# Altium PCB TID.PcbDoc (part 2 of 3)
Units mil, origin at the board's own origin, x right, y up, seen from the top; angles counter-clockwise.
Board outline 3200 x 2650 mil, 4 copper layers (Top Layer, Mid-Layer 1, Mid-Layer 2, Bottom Layer), stack 61.2 mil thick; 193 components, 108 nets, 523 pads, 202 vias.
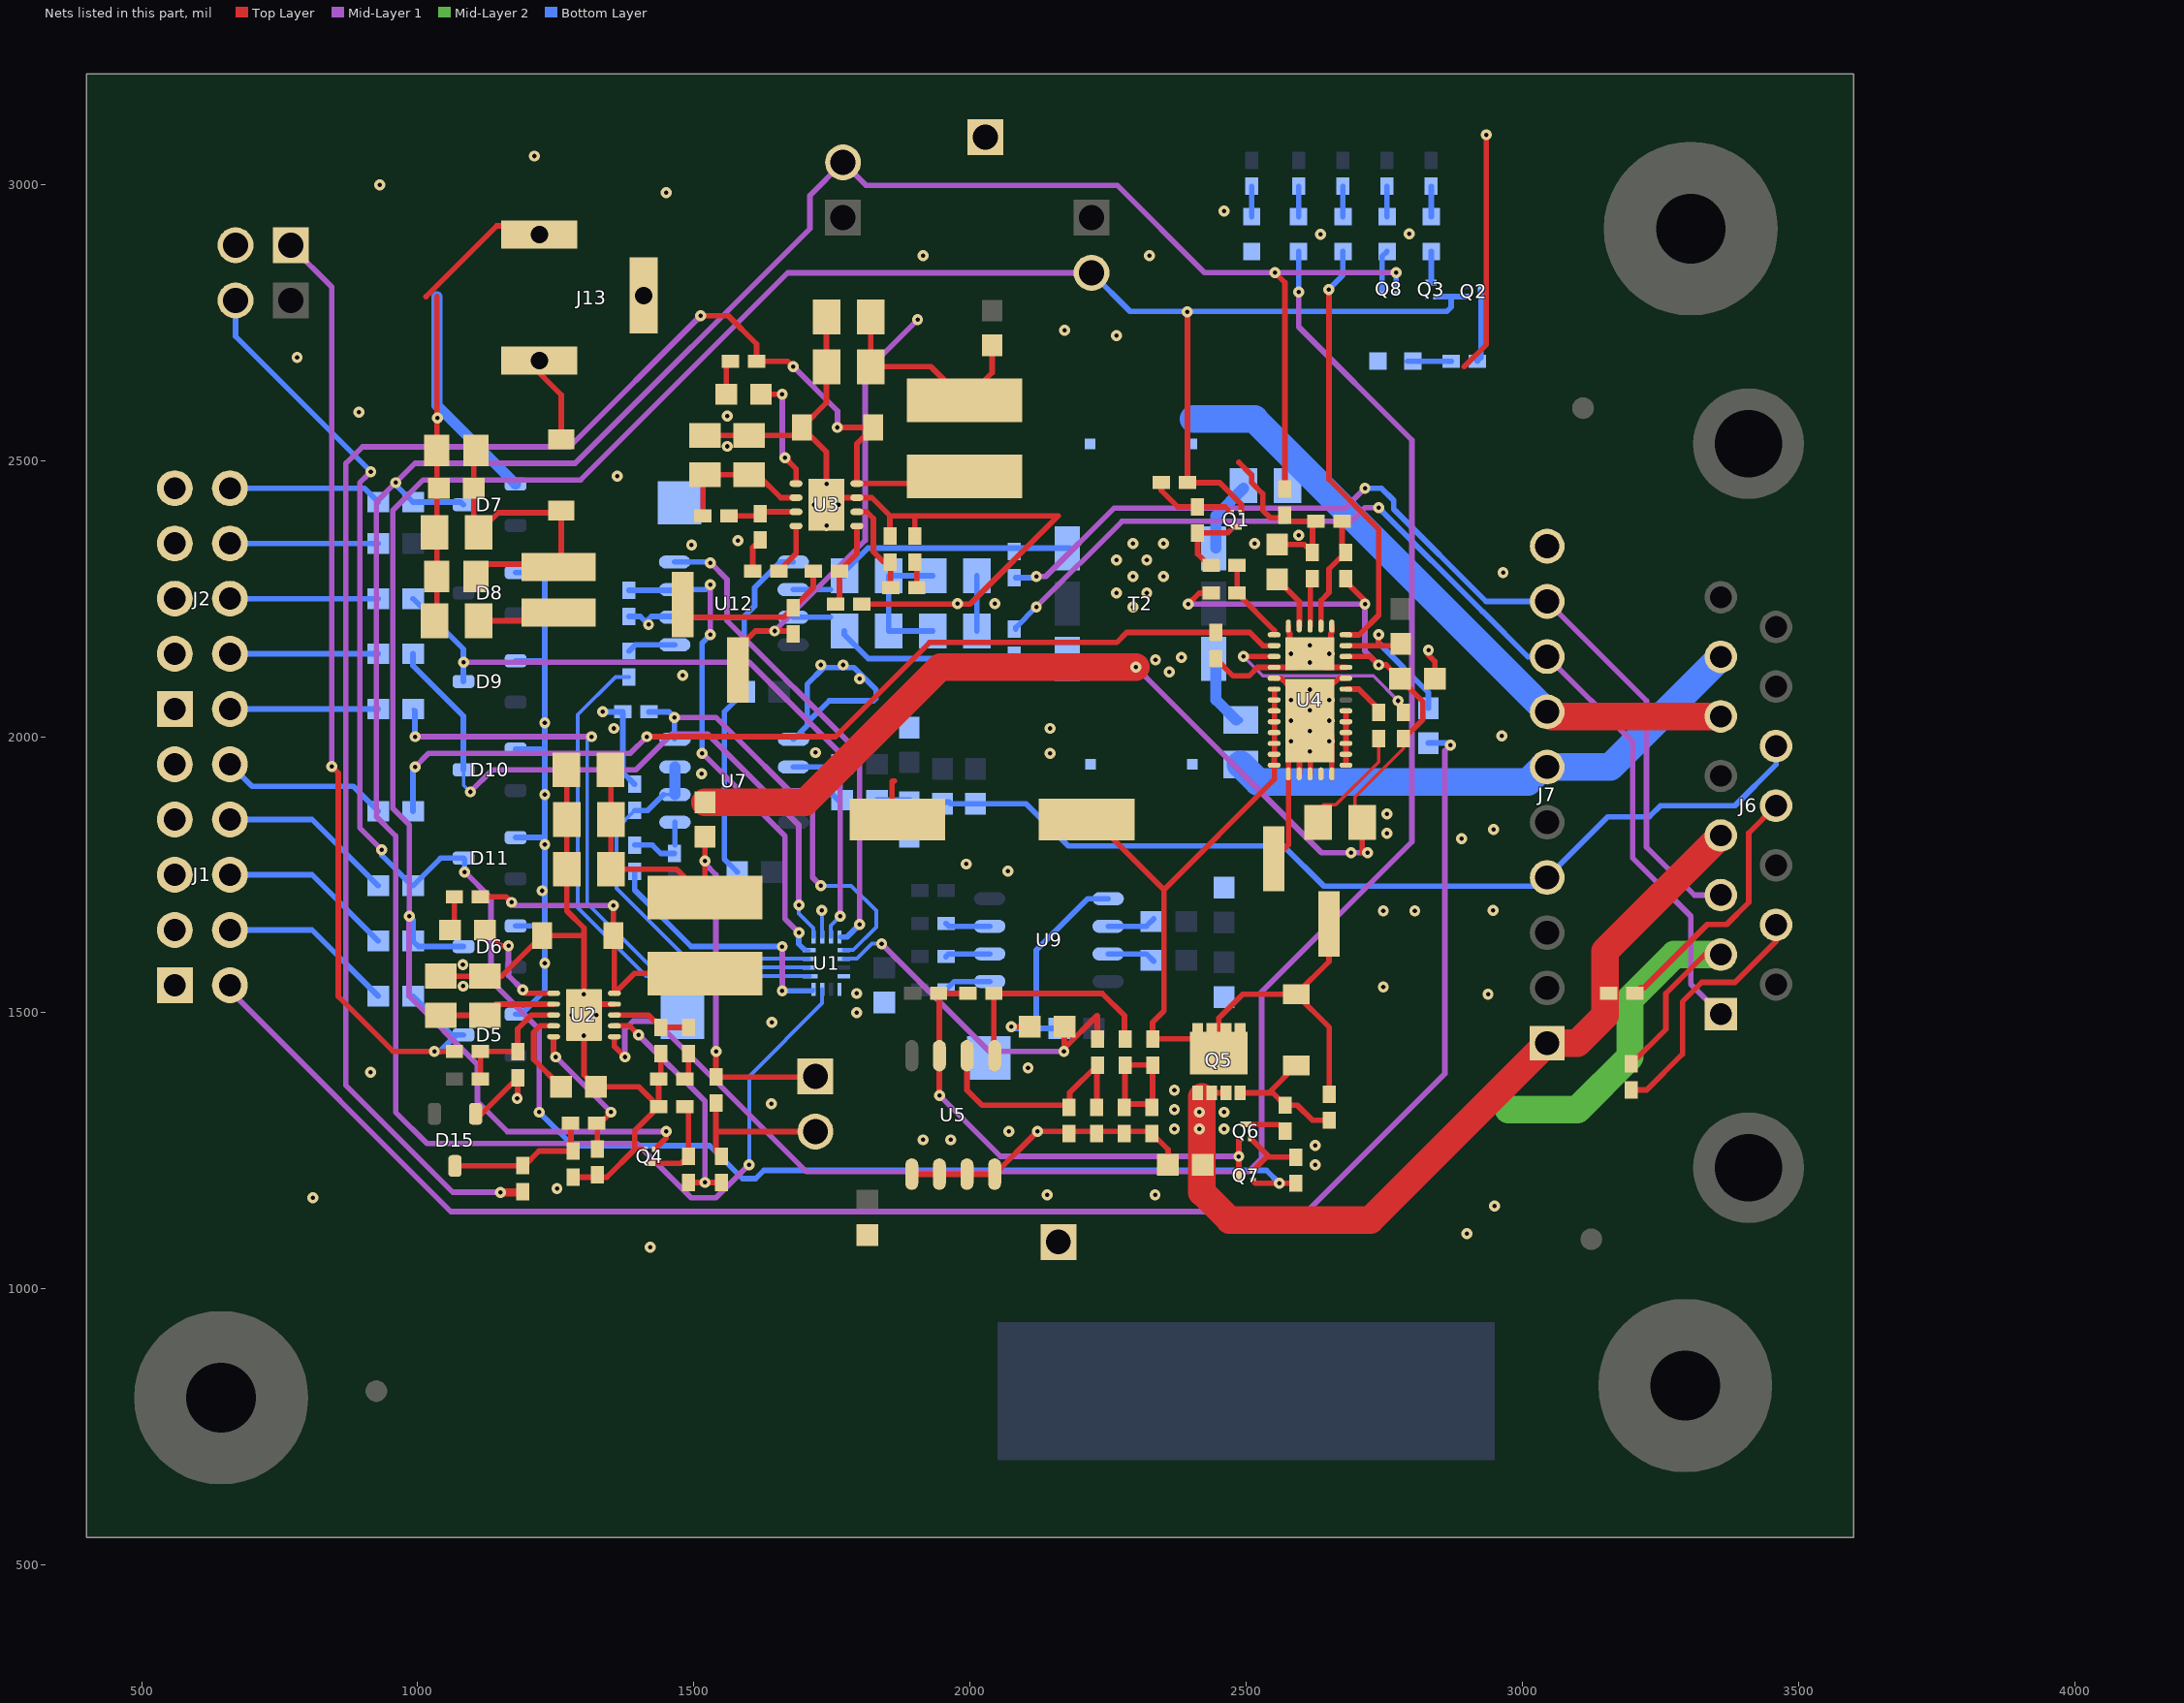
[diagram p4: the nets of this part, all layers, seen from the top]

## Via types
v1: diameter 20, hole 8, Top Layer to Bottom Layer, 200 vias
v2: diameter 19, hole 7.87, Top Layer to Bottom Layer, 2 vias

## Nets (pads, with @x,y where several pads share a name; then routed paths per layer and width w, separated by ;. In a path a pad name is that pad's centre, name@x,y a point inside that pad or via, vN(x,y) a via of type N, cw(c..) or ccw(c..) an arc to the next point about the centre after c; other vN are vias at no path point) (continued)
DATA-: C27.2 J6.13 J7.4 R22.2 R44.2 R62.2 | length 1817
  Bottom Layer w10: R62.2@1831.5,1885 1891.5,1885 1895,1881.5 1962.01,1881.5 1965,1878.5 2101.5,1878.5 2177.75,1802.25 2567.75,1802.25 2640.71,1729.29 3029.29,1729.29 J7.4@3045,1745 3155,1855 3230,1855 3250,1875 3385,1875 3459.37,1949.37 J6.13@3459.37,1982.87
DATA_IN: R56.1 U1.16 | length 481.3
  Mid-Layer 1 w10: v1(1660,1540) v1(1660,1620)
  Bottom Layer w6: U1.16@1713.62,1540 U1.16@1716.38,1542.76
  Bottom Layer w10: R56.1@1392.82,1756.47 1392.82,1722.18 1495,1620 1650,1620 v1(1660,1620) ; v1(1660,1540) U1.16@1713.62,1540
DATA_OUT: R67.2 U1.9 U7.4 | length 773.8
  Mid-Layer 1 w10: v1(1465,2035) 1540,2035 1715,1860 1715,1745 v1(1730,1730)
  Bottom Layer w6: U7.4@1465,1995.95 U7.4@1465.85,1995.09
  Bottom Layer w7: v1(1730,1730) 1785,1730 1830,1685 1830,1655 1788.62,1613.62 U1.9@1771.5,1613.62
  Bottom Layer w10: R67.2@1418.62,2045 1455,2045 v1(1465,2035) U7.4@1465,1995.95
DSL2+: C35.1 J6.6 J7.7 L5.2 | length 1177.3
  Top Layer w50: J7.7@3045,2045 3053.19,2036.81 J6.6@3359.37,2036.81
  Bottom Layer w50: 2405,2575 2515,2575 J7.7@3045,2045
DSL2-: C33.1 J6.7 J7.6 L4.1 | length 976.2
  Bottom Layer w50: C33.1@2490,1950 2521.64,1918.36 3010.29,1918.36 3036.93,1945 J7.6@3045,1945 3159.69,1945 J6.7@3359.37,2144.68
DSL4+: J6.3 J7.9 R72.2 | length 1823.7
  Mid-Layer 1 w10: v1(2120,2290) 2136.96,2290 2260.62,2413.66 2678.66,2413.66 v1(2715,2450) ; J7.9@3045,2245 3225,2065 3225,1800 3311.81,1713.19 J6.3@3359.37,1713.19
  Bottom Layer w10: R72.2@2082.82,2287.77 2117.77,2287.77 v1(2120,2290) ; v1(2715,2450) 2745,2450 2767.22,2427.78 2767.22,2412.22 2934.45,2245 J7.9@3045,2245 J7.9@3037.62,2237.62
DSL4-: J6.1 J7.8 R71.2 | length 1945
  Mid-Layer 1 w10: v1(2120,2235) 2275,2390 2690,2390 2715,2415 v1(2740,2415) ; J7.8@3045,2145 3200,1990 3200,1780 3305,1675 3305,1551.81 J6.1@3359.37,1497.44
  Bottom Layer w10: R71.2@2082.82,2195.02 2082.82,2197.82 v1(2120,2235) ; v1(2740,2415) 2746.89,2408.11 2746.89,2407.28 2927.04,2227.13 2927.87,2227.13 3010,2145 J7.8@3045,2145
DSL_EN: R84.2 U1.4 U12.3 | length 903.1
  Mid-Layer 1 w10: v1(1515,1970) 1665,1820 1665,1670 v1(1690,1645) ; v1(1530,2185) v1(1530,2275)
  Bottom Layer w6: v1(1530,2185) v1@1535,2185 ; U1.4@1701.57,1613.62 U1.4@1708.5,1613.62
  Bottom Layer w10: R84.2@1382.5,2265.02 U12.3@1463.84,2265.02 ; U12.3@1465.22,2266.39 1521.39,2266.39 v1(1530,2275) ; v1(1515,1970) 1515,2170 v1(1530,2185) ; v1(1690,1645) 1690,1624.74 U1.4@1698.83,1615.92
DSL_IN: R79.1 U1.1 | length 943.6
  Bottom Layer w6: U1.1@1709.54,1567.31 U1.1@1710.47,1566.38
  Bottom Layer w7: R79.1@1382.5,2107.77 1357.77,2107.77 1290,2040 1290,1690 1413.62,1566.38 U1.1@1710.47,1566.38
DSL_OUT: U1.8 U12.4 | length 877.3
  Mid-Layer 1 w10: v1(1530,2315) 1560,2285 1560,2210 1800,1970 v1(1800,1660)
  Bottom Layer w6: U12.4@1465.22,2316.39 U12.4@1466.61,2315 ; v1@1528.61,2316.39 v1(1530,2315)
  Bottom Layer w10: U12.4@1465.22,2316.39 v1@1528.61,2316.39 ; U1.8@1766.34,1637.43 1766.53,1637.24 1777.24,1637.24 v1(1800,1660)
EFUSE_PGOOD: D20.1 U4.31 | length 780.6
  Top Layer w10: v1(2649.5,2809.99) 2650.16,2809.33 2650.16,2465.82 2740,2375.98 2740,2220 2704.47,2184.47 U4.31@2681.02,2184.47
  Bottom Layer w10: v1(2649.5,2809.99) 2675.09,2835.58 D20.1@2675.09,2878.79
EN_TX_DATA: R68.2 U1.3 U7.2 U7.3 | length 692.4
  Bottom Layer w6: U7.2@1445.09,1895.09 U7.2@1465.85,1895.09 ; U1.3@1707.57,1598.81 U1.3@1708.5,1597.87
  Bottom Layer w7: R68.2@1392.82,1866.47 1360,1833.65 1360,1725 1487.13,1597.87 U1.3@1708.5,1597.87
  Bottom Layer w10: R68.2@1392.82,1866.47 1416.47,1866.47 U7.2@1445.09,1895.09
  Bottom Layer w20: U7.2@1465.85,1895.09 U7.3@1465.85,1945.09
GND: C2.2 C3.2 C4.2 C5.2 C6.2 C7.2 C8.2 C9.2 C11.2 C12.2 C13.2 C14.2 C15.2 C16.2 C17.2 C18.2 C19.2 C20.2 C21.2 C22.2 C23.2 C24.2 C25.1 C26.1 C27.1 C28.2 C29.1 C30.2 C31.1 C32.2 C34.2 C36.2 C38.2 C39.1 C40.1 C41.1 C42.1 D2.1 D5.1 D6.1 D7.1 D8.1 D9.1 D10.1 D11.1 D14.2 D15.1 D16.2 D17.1 J1.1 J1.3 J1.5 J1.7 J1.9 J2.1 J2.3 J2.5 J2.7 J2.9 J6.2 J7.10 J8.2 J12.1 J13.2 J13.3 J16.1 L4.2 Q1.2 Q3.2 Q4.2 Q6.2 Q7.2 Q8.2 R16.1 R19.1 R20.1 R29.2 R30.1 R35.1 R36.1 R40.1 R46.1 R48.1 R49.1 R52.1 R61.1 R67.1 R68.1 R70.1 R83.1 R84.1 R85.1 R86.1 TP1.1 TP2.1 TP3.1 U1.6 U1.12 U1.13 U2.9 U2.11 U3.7 U3.9 U4.4 U4.28 U4.32 U4.36 U4.37 U5.1 U5.2 U5.3 U5.4 U7.5 U9.5 U12.2 U12.5 | length 10271.4
  Top Layer w10: 1014.96,2797 1142.96,2925 J13.2@1200,2925 ; C19.2@1030,2210 1034.57,2214.56 C16.2@1034.57,2290 1034.57,2374.56 C30.2@1034.57,2518.7 1034.57,2796.61 1034.96,2797 ; C6.2@1041.8,1566.3 C5.2@1121.8,1566.3 1151.83,1566.3 D14.2@1225.53,1640 1301.05,1640 ; D15.1@1107.4,1317.24 1115.9,1317.24 R19.1@1181.05,1382.4 1181.05,1346.05 v1(1180,1345) ; C34.2@1270,1940 1270,1850 C3.2@1270,1760 1270,1684.47 1301.05,1653.42 1301.05,1640 ; R30.1@1281.05,1202.4 1342.4,1202.4 1392.8,1252.8 ; U2.11@1320.73,1515.7 U2.9@1356.17,1515.7 ; Q4.2@1410.87,1252.8 1392.8,1252.8 ; C8.2@1440,1426.38 1440,1383.62 C9.2@1436.38,1380 R29.2@1436.38,1330 ; C11.2@1520,2545.43 C12.2@1600,2545.43 1680.96,2545.43 D16.2@1695.53,2560 ; R36.1@1606.38,2300 1606.38,2342.76 R35.1@1620,2356.38 ; C13.2@1740,2760 C14.2@1740,2670 1740,2604.47 D16.2@1695.53,2560 ; R40.1@1803.62,2240 2000,2240 2160,2400 1900,2400 ; C15.2@1855,2363.62 1855,2400 ; C22.2@1858.74,1850 1858.74,1918.74 1859.72,1919.72 1863.36,1919.72 ; U5.1@1894.5,1207.72 U5.2@1944.5,1207.72 U5.3@1994.5,1207.72 U5.4@2044.5,1207.72 v1(2122.2,1285.41) C24.2@2330.6,1285.41 ; C20.2@1900,2363.62 1900,2400 ; v1(2075,1475) C31.1@2108,1475 ; C24.2@2329.5,1281.38 2358.5,1252.37 C21.2@2358.5,1225 C21.2@2353.5,1220 ; R85.1@2346.38,2460 2346.38,2446.06 2376.22,2416.22 R86.1@2412.13,2416.22 2462.17,2416.22 Q1.2@2472.99,2405.39 ; R46.1@2445,2141.38 2476.38,2110 2505,2110 2520.41,2125.41 U4.37@2591.73,2125.41 ; 2486.74,2496.74 2510,2473.48 2510,2460 2530,2440 2530,2410 2543.62,2396.38 2570,2396.38 2576.38,2390 R49.1@2626.38,2390 2620,2383.62 R48.1@2620,2333.62 2605.77,2347.85 C23.2@2556.06,2347.85 ; Q6.2@2508.63,1272.2 2542.22,1238.62 ; Q7.2@2512.3,1214.13 2536.78,1238.62 2542.22,1238.62 ; U4.36@2576.69,2200.22 2576.69,2189.11 2578.78,2187.03 U4.37@2578.78,2175.53 ; R52.1@2589.5,1238.62 2542.22,1238.62 ; U4.37@2640.39,2125.41 U4.28@2681.02,2125.41 ; U4.37@2653.35,2175.53 2653.35,2187.03 2655.43,2189.11 U4.32@2655.43,2200.22 ; v1(2830,2156.5) 2830,2147.99 2841.5,2136.5 C25.1@2841.5,2105 ; 2895,2670 2935,2710 v1(2935,3090) ; R70.1@3197.27,1407.48 3260,1470.21 3260,1535 3330.32,1605.32 J6.2@3359.37,1605.32 ; 1301.05,1640 U2.11@1301.05,1496.02 1301.05,1387.52 C7.2@1322.54,1366.02 1400.36,1366.02 R29.2@1436.38,1330 ; 1392.8,1252.8 1392.8,1286.42 R29.2@1436.38,1330 ; D16.2@1695.53,2560 1740,2515.53 U3.9@1740,2420 1752.8,2432.8 U3.7@1795.12,2432.8 1822.2,2432.8 1855,2400 ; 1855,2400 1900,2400
  Mid-Layer 2 w50: 2975,1325 3100,1325 3195,1420 3195,1525 3275.32,1605.32 J6.2@3359.37,1605.32
  Bottom Layer w6: v1(1731.92,1685.6) 1731.92,1673.08 1732.13,1672.87
  Bottom Layer w7: U1.6@1732.13,1637.24 1732.13,1672.87
  Bottom Layer w10: D5.1@1177.24,1497.4 1187.4,1497.4 1230,1540 1230,2285 1217.6,2297.4 D8.1@1177.24,2297.4 ; D6.1@1177.24,1657.4 1227.4,1657.4 ; D11.1@1177.24,1817.4 1227.4,1817.4 ; D10.1@1177.24,1977.4 1227.4,1977.4 ; D9.1@1177.24,2137.4 1227.4,2137.4 ; v1(1335,2045) R67.1@1371.38,2045 1371.38,1935.16 R68.1@1392.82,1913.72 ; R84.1@1382.5,2217.77 1402.84,2217.77 1417.72,2202.9 v1(1417.94,2202.9) 1417.94,2212.53 1423.17,2217.77 U12.2@1463.84,2217.77 ; U12.2@1465.22,2216.39 1589.93,2216.39 ; C39.1@1578.5,1755 1555,1778.5 1555,2045.07 C40.1@1591.32,2081.39 1591.32,2215 1589.93,2216.39 ; U12.5@1679.79,2316.39 1656.39,2316.39 1610,2270 1610,2236.46 1589.93,2216.39 ; U7.5@1680.42,1995.09 1705,2019.68 1705,2025 ; C36.2@2012.5,2191.39 C38.2@2012.5,2291.39 ; v1(2075,1475) 2078.29,1471.71 2120,1471.71 ; C41.1@2161.32,1471.71 2120,1471.71 ; U9.5@2250.1,1706.71 2213.29,1706.71 2120,1613.42 2120,1471.71 ; J7.10@3045,2345 J7.10@3046.38,2346.38 ; 1705,2025 1745,2065 1825,2065 1830,2070 1830,2085 1790,2125 1735,2125 1705,2095 1705,2025
  Bottom Layer w20: 1034.96,2797 1034.96,2599.69 D7.1@1177.24,2457.4
  other v1: 1421.24,1075.75 2900,1100 2950,1150 810,1165 2140,1170 2335,1170 1252.05,1181.67 2625,1225 2625.33,1259.67 1915,1270 1965,1270 2070,1285 1640,1335 914.44,1392.07 2104.97,1400.56 1301.05,1458.62 1641.21,1482.42 1278.41,1496.02 1323.69,1496.02 1795,1500 1301.05,1533.42 2937.93,1533.32 1795,1535 2748.33,1546.61 1081.93,1548.19 1081.73,1587.46 1230,1590 2748.33,1684.77 2805.34,1684.77 2946.88,1685.27 1225.19,1721.02 2068.62,1756.26 1992.78,1769.33 1230,1805 2889.87,1815.49 2947.96,1831.83 1230,1895 1514.17,1932.98 2145,1970 1720.32,1971.2 2962.62,2001.62 1355,2015 2145,2015 1230,2025 1800,2105 1479.4,2111.23 1730,2130 1770,2130 2615.71,2134.38 2581.26,2150.13 2650.16,2150.13 2615.71,2165.87 1977.61,2240.9 2045.19,2240.65 2965.14,2297.36 1495.87,2347.08 2515,2350 1580,2355 2595,2365 1740,2382.6 1717.36,2420 1762.64,2420 1740,2457.4 1361.48,2471.59 1560.15,2525.8 1035.82,2577.38 1560.15,2580.52 893.6,2587.4 781.53,2686.81 2265.46,2725.97 2171.26,2735.68 1914.69,2870.98 2325.01,2870.92 2634.61,2909.71 2795.4,2910.41 2459.71,2952.02 1450,2985 931.19,2999.24 1211.13,3051.47
HI_V_SEL: D6.3 J9.2 Q1.1 Q2.1 Q3.1 Q4.1 R7.2 R85.2 | length 4320.2
  Top Layer w10: Q4.1@1429.13,1252.8 1450,1273.66 v1(1450,1285) ; J9.2@2220,2840 J9.2@2220.53,2840.53 ; v1@2393.2,2769.38 v1(2393.62,2768.96) R85.2@2393.62,2460 2452.13,2460 2491.26,2420.87 Q1.1@2491.26,2405.39
  Mid-Layer 1 w10: v1(1450,1285) 1162.22,1285 1108.11,1339.11 1108.11,1406.46 984.29,1530.28 984.29,1674.29 v1(985,1675) 985,1840 955,1870 955,2410 1010,2465 1295,2465 1670,2840 J9.2@2220,2840
  Bottom Layer w10: v1(985,1675) 991.5,1668.5 R7.2@991.5,1630 1001.5,1620 D6.3@1082.76,1620 ; J9.2@2220,2840 2289.82,2770.18 2863.37,2770.18 2871.08,2777.89 2871.08,2797.06 ; 2845.1,2797.06 2871.08,2797.06 ; Q2.1@2897.05,2797.06 2871.08,2797.06
HIPERFACE: D7.3 J10.2 Q8.1 R12.2 R83.2 U1.15 | length 5004.1
  Top Layer w10: v1(2551.95,2840.61) 2570,2822.56 R83.2@2570,2448.62
  Mid-Layer 1 w10: v1(1600,1225) 1540,1165 1495.24,1165 1396.92,1263.33 1016.67,1263.33 960,1320 960,1820 925,1855 925,2425 v1(960,2460) 995.01,2495.01 1285.01,2495.01 1710,2920 1710,2980 J10.2@1770,3040 1811.48,2998.52 2266.48,2998.52 2424.53,2840.47 2771.17,2840.47 v1(2771.45,2840.19)
  Bottom Layer w7: v1(1600,1225) 1600,1385 1732.13,1517.13 U1.15@1732.13,1542.76
  Bottom Layer w10: v1(960,2460) 960,2456.5 R12.2@991.5,2425 1077.76,2425 D7.3@1082.76,2420 ; v1@2771.3,2840.34 v1(2771.45,2840.19) ; Q8.1@2771.51,2819.62 v1@2771.51,2842.57
LOAD_SW_CTRL: D11.3 J11.2 Q7.1 R9.2 R52.2 | length 3326.8
  Top Layer w10: Q7.1@2512.3,1195.87 2516.78,1191.38 v1(2560,1191.38) R52.2@2589.5,1191.38 R52.2@2582.77,1198.11
  Mid-Layer 1 w10: v1@910,2475 895,2460 895,1835 v1(935,1795) ; v1(1085,1755) 1132.57,1707.43 1132.57,1557.71 1220,1470.28 v1(1220,1320)
  Bottom Layer w10: J11.2@670,2790 670,2725 v1(915,2480) ; v1(935,1795) 935,1785.03 990.03,1730 R9.2@991.5,1730 1041.5,1780 D11.3@1082.76,1780 1085,1777.76 v1(1085,1755) ; v1(1220,1320) 1280.65,1259.35 1528.32,1259.35 1588.08,1199.6 1611.64,1199.6 1626.8,1214.76 2536.62,1214.76 v1(2560,1191.38)
NetC1_1: C1.1 R18.1 | length 73.3
  Top Layer w10: C1.1@1058.5,1640 1066.38,1647.87 R18.1@1066.38,1710
NetC1_2: C1.2 U2.1 | length 211.3
  Top Layer w10: C1.2@1123.05,1650 C1.2@1121.5,1650 1149.87,1621.63 v1(1164.27,1621.63) ; v1(1190,1541.58) 1190,1540 1194.61,1535.39 U2.1@1245.93,1535.39
  Mid-Layer 1 w10: v1@1162.95,1617.05 1164.27,1618.37 v1(1164.27,1621.63) ; v1(1164.27,1621.63) 1164.28,1567.3 v1(1190,1541.58)
NetC2_1: C2.1 C3.1 C34.1 J3.1 L1.2 R17.1 R24.2 | length 1016.2
  Top Layer w10: C34.1@1350,1940 1350,1850 C3.1@1350,1760 1468.9,1760 L1.2@1509.45,1719.45 ; L1.2@1520,1730 R17.1@1520,1818.5 ; v1(1540,1430) R24.2@1540,1383.62 1693.62,1383.62 J3.1@1710,1400
  Mid-Layer 1 w10: v1@1520,1770 1540,1750 v1(1540,1430)
  other v1: 1520,1775
NetC4_1: C4.1 R16.2 R50.1 U5.6 | length 427.3
  Top Layer w10: U5.6@1994.5,1422.28 1994.5,1360 2021.84,1332.66 2180.6,1332.66 2180.6,1355.41 2229.5,1404.31 C4.1@2229.5,1328.62
NetC7_1: C7.1 U2.4 | length 159.9
  Top Layer w10: U2.4@1245.93,1476.33 1221.81,1476.33 1210,1464.52 1210,1415.57 C7.1@1259.55,1366.02
NetC8_1: C8.1 R26.2 U2.8 | length 143.1
  Top Layer w10: U2.8@1356.17,1496.02 1417.6,1496.02 C8.1@1440,1473.62 R26.2@1490,1473.62
NetC9_1: C9.1 R26.1 | length 49
  Top Layer w10: C9.1@1483.62,1380 1490,1386.38 R26.1@1490,1426.38
NetC10_1: C10.1 R31.1 | length 63.3
  Top Layer w10: C10.1@1558.5,2620 1558.5,2672.13 R31.1@1566.38,2680
NetC10_2: C10.2 U3.1 | length 210.4
  Top Layer w10: C10.2@1621.5,2620 v1(1660,2620) ; v1(1665,2505) 1684.88,2485.12 U3.1@1684.88,2458.39
  Mid-Layer 1 w10: v1(1660,2620) 1660,2510 v1(1665,2505)
NetC13_1: C13.1 C14.1 J5.1 L2.2 R32.1 R39.2 | length 1242.7
  Top Layer w10: J5.1@1580,2100 J5.1@1593.62,2100 ; J5.1@1580,2122.5 1580,2160 1611.39,2191.39 v1(1646.08,2191.39) 1674.98,2191.39 R39.2@1680,2186.38 ; C13.1@1820,2760 C14.1@1820,2670 1928.9,2670 L2.2@1990,2608.9 1994.72,2613.62 2040,2658.9 R32.1@2040,2708.5
  Mid-Layer 1 w10: v1(1646.08,2191.39) 1810,2355.32 1810,2660 v1(1905,2755)
NetC15_1: C15.1 R37.2 U3.6 | length 179.6
  Top Layer w10: U3.6@1795.12,2407.2 1812.8,2407.2 1825,2395 1825,2335 1843.62,2316.38 C15.1@1855,2316.38 1856.38,2315 R37.2@1856.38,2270
NetC16_1: C16.1 C17.1 C18.1 C30.1 D18.1 L6.1 | length 589.6
  Top Layer w10: C16.1@1105.44,2290 1128,2312.56 1270,2312.56 1260,2322.56 1260,2405.53 1145.54,2405.53 C17.1@1110,2370 1101.5,2378.5 C18.1@1101.5,2450 1101.5,2514.76 C30.1@1105.44,2518.7
NetC20_1: C20.1 R37.1 | length 47.9
  Top Layer w10: C20.1@1900,2316.38 1903.62,2312.76 R37.1@1903.62,2270
NetC23_1: C23.1 U4.35 | length 101.3
  Top Layer w10: C23.1@2556.06,2284.86 2596.38,2244.55 U4.35@2596.38,2200.22
NetC24_1: C24.1 R59.1 R60.1 R61.2 | length 245.4
  Top Layer w10: C24.1@2329.5,1335 2282.94,1335 2280.6,1332.66 R59.1@2280.6,1405.41 R60.1@2330.6,1405.41 C24.1@2330.6,1332.66
NetC33_2: C33.2 T2.6 | length 134.6
  Bottom Layer w10: C33.2@2482,2030 C33.2@2490,2030
  Bottom Layer w20: T2.6@2445.32,2141.39 2445.32,2066.68 C33.2@2482,2030
NetC35_2: C35.2 T2.4 | length 134.2
  Bottom Layer w10: C35.2@2495,2450 C35.2@2500,2450
  Bottom Layer w20: T2.4@2445.32,2341.39 2445.32,2400.32 C35.2@2495,2450
NetC36_1: C36.1 C38.1 R80.1 R82.2 | length 260
  Bottom Layer w10: C36.1@1932.5,2191.39 R80.1@1852.5,2191.39 R82.2@1852.5,2291.39 C38.1@1932.5,2291.39
NetD1_1: D1.1 Q3.3 | length 56.3
  Bottom Layer w10: Q3.3@2834.9,2822.62 2835.09,2822.82 D1.1@2835.09,2878.79
NetD1_2: D1.2 R3.1 | length 54.9
  Bottom Layer w10: D1.2@2835.09,2941.78 R3.1@2835.09,2996.67
NetD2_2: D2.2 R4.1 | length 79.2
  Bottom Layer w10: D2.2@2792.16,2680 D2.2@2801.5,2680 R4.1@2871.38,2680
NetD13_2: D13.2 R13.1 | length 54.9
  Bottom Layer w10: D13.2@2595.09,2941.78 R13.1@2595.09,2996.67
NetD14_1: D14.1 L1.1 R18.2 U2.10 | length 563.3
  Top Layer w10: R18.2@1113.62,1710 1160,1710 v1(1170,1700) ; D14.1@1354.47,1640 v1(1354.47,1694.47) ; D14.1@1356.17,1618.3 U2.10@1356.17,1535.39 1391.88,1571.1 L1.1@1520,1571.1
  Mid-Layer 1 w10: v1(1170,1700) 1175.53,1694.47 v1(1354.47,1694.47)
NetD15_3: D15.3 R25.1 R27.2 R30.2 | length 280.1
  Top Layer w10: D15.3@1070,1222.76 1192.76,1222.76 1219.64,1249.64 R30.2@1281.05,1249.64 1277.43,1253.26 R25.1@1277.43,1306.02
NetD17_2: D17.2 R34.1 | length 54.9
  Bottom Layer w10: D17.2@2510.05,2941.78 R34.1@2510.05,2996.67
NetD18_2: D18.2 J13.1 | length 169.4
  Top Layer w10: J13.1@1200,2679 1260,2619 D18.2@1260,2534.47
NetD19_1: D19.1 Q8.3 | length 72.3
  Bottom Layer w10: Q8.3@2745.86,2810.35 2745.86,2869.56 D19.1@2755.09,2878.79
NetD19_2: D19.2 R81.1 | length 54.9
  Bottom Layer w10: D19.2@2755.09,2941.78 R81.1@2755.09,2996.67
NetD20_2: D20.2 R43.1 | length 54.9
  Bottom Layer w10: D20.2@2675.09,2941.78 R43.1@2675.09,2996.67
NetD21_2: D21.2 Q5.4 R45.1 R47.2 | length 252.2
  Top Layer w10: Q5.4@2488.99,1355.06 2541.09,1355.06 ; D21.2@2590.6,1404.57 2541.09,1355.06 ; R45.1@2650.6,1305.41 2619.91,1305.41 2592.67,1332.66 R47.2@2570.6,1332.66 2548.2,1355.06 2541.09,1355.06
NetJ1_2: J1.2 R1.1 | length 3119.8
  Mid-Layer 1 w10: J1.2@660,1550 660,1540 1060,1140 2610,1140 2859.76,1389.76 2859.76,1974.76 v1(2870,1985)
  Bottom Layer w6: v1@2866.5,1988.5 v1(2870,1985)
  Bottom Layer w10: R1.1@2830,1988.5 v1@2866.5,1988.5
NetJ1_4: J1.4 R5.1 | length 318.2
  Bottom Layer w10: J1.4@660,1650 808.5,1650 R5.1@928.5,1530
NetJ1_6: J1.6 R7.1 | length 318.2
  Bottom Layer w10: J1.6@660,1750 808.5,1750 R7.1@928.5,1630
NetJ1_8: J1.8 R9.1 | length 318.2
  Bottom Layer w10: J1.8@660,1850 808.5,1850 R9.1@928.5,1730
NetJ1_10: J1.10 R11.1 | length 303.7
  Bottom Layer w10: J1.10@660,1950 700,1910 883.5,1910 R11.1@928.5,1865
NetJ2_2: J2.2 R2.1 | length 268.5
  Bottom Layer w10: J2.2@660,2050 R2.1@928.5,2050
NetJ2_4: J2.4 R6.1 | length 268.5
  Bottom Layer w10: J2.4@660,2150 R6.1@928.5,2150
NetJ2_6: J2.6 R8.1 | length 268.5
  Bottom Layer w10: J2.6@660,2250 R8.1@928.5,2250
NetJ2_8: J2.8 R10.1 | length 268.5
  Bottom Layer w10: J2.8@660,2350 R10.1@928.5,2350
NetJ2_10: J2.10 R12.1 | length 278.9
  Bottom Layer w10: J2.10@660,2450 903.5,2450 R12.1@928.5,2425
NetJ3_2: J3.2 R23.1 R24.1 | length 280.4
  Top Layer w10: R24.1@1540,1336.38 1540,1249.84 R23.1@1550,1239.84 ; 1540.23,1284.78 J3.2@1720,1285
NetJ5_2: J5.2 R38.2 R39.1 | length 273.6
  Top Layer w10: J5.2@1495,2216.39 1662.77,2216.39 R39.1@1680,2233.62 1716.38,2270 R38.2@1716.38,2300
NetJ6_10: J6.10 R70.2 | length 459.1
  Top Layer w10: R70.2@3197.27,1360.24 3225.24,1360.24 3290,1425 3290,1520 3325,1555 3385,1555 3459.37,1629.37 J6.10@3459.37,1659.25
NetJ6_12: J6.12 R69.2 | length 470.2
  Top Layer w10: R69.2@3203.62,1535 3213.62,1545 3220,1545 3335,1660 3370,1660 3410,1700 3410,1825.63 J6.12@3459.37,1875
NetJ15_1: J15.1 R21.2 R42.1 U4.5 U4.14 U4.15 U4.16 U4.17 U4.18 U4.27 U4.38 | length 880.4
  Top Layer w6: 2640,1876.51 2662.31,1876.51 2740,1954.2 R21.2@2740,1996.38
  Top Layer w10: J15.1@2550,1777.5 2576.69,1804.19 U4.38@2576.69,1989.31 ; U4.5@2551.1,2105.73 2563.39,2105.73 ; 2565.48,2103.64 2575.79,2093.33 U4.38@2575.79,2068.96 ; U4.38@2580,2064.74 U4.38@2616.06,2028.68 ; U4.38@2580.28,1992.89 U4.38@2596.38,2009 ; U4.15@2596.38,1932.5 U4.38@2596.38,2009 ; U4.16@2616.06,1932.5 U4.38@2616.06,2028.68 ; U4.38@2616.06,2040.77 U4.38@2616.06,2028.68 ; R42.1@2630,1845 R42.1@2630,1855 ; U4.38@2635.75,2009 U4.38@2655.43,1989.31 ; U4.38@2653.89,2094.03 2668.73,2105.73 U4.27@2681.02,2105.73 ; U4.18@2654.83,1924.8 U4.38@2654.83,2001.3 ; U4.38@2596.38,2009 U4.38@2616.06,2028.68
  other v1: 2615.71,1972.96 2581.26,1991.66 2650.16,1991.66 2615.71,2010.36 2581.26,2029.06 2650.16,2029.06 2615.71,2047.76 2581.26,2066.46 2650.16,2066.46 2615.71,2085.16
NetQ1_3: Q1.3 R55.1 R86.2 | length 145.6
  Top Layer w10: R55.1@2436.38,2310 2432.85,2310 2412.13,2330.72 R86.2@2412.13,2368.98 2466.41,2368.98 2477.24,2379.8 Q1.3@2482.13,2379.8
NetQ2_3: Q2.3 R4.2 | length 128.9
  Bottom Layer w10: R4.2@2918.62,2680 2924.98,2686.35 Q2.3@2924.98,2806.25
NetQ4_3: Q4.3 R28.2 R29.1 | length 167.9
  Top Layer w10: Q4.3@1420,1227.2 1477.2,1227.2 R28.2@1490,1240 1490,1323.62 R29.1@1483.62,1330
NetQ6_1: Q6.1 Q7.3 R51.1 R57.2 U5.7 | length 891.8
  Top Layer w10: R51.1@1943.12,1535 R57.2@1995.88,1535 ; v1(1944.5,1350.5) U5.7@1944.5,1422.28 R51.1@1944.5,1533.62 ; Q7.3@2486.7,1205 v1(2486.7,1240) 2486.7,1270.39 2488.52,1272.2
  Mid-Layer 1 w10: v1(1944.5,1350.5) 2055,1240 v1(2486.7,1240)
NetQ6_3: Q6.3 R47.1 | length 76.2
  Top Layer w10: Q6.3@2499.5,1297.8 2558.22,1297.8 R47.1@2570.6,1285.41
NetR14_1: R14.1 R15.1 R19.2 U2.3 | length 234.2
  Top Layer w10: R14.1@1113.62,1380 R15.1@1113.62,1430 1180.69,1430 R19.2@1181.05,1429.64 1181.05,1471.05 1206.02,1496.02 U2.3@1245.93,1496.02
NetR20_2: R20.2 R25.2 U2.5 | length 265.4
  Top Layer w10: U2.5@1245.93,1456.65 1245.93,1424.07 v1(1250,1420) ; R20.2@1323.62,1255 R20.2@1325,1253.62 1325,1305.69 1324.67,1306.02 1336.02,1306.02 v1(1350,1320)
  Mid-Layer 1 w10: v1(1250,1420) v1(1350,1320)
NetR21_1: R21.1 U4.26 | length 73.9
  Top Layer w10: U4.26@2681.02,2086.04 2703.96,2086.04 R21.1@2740,2050
NetR23_2: R23.2 R28.1 U2.7 | length 427.6
  Top Layer w10: U2.7@1356.17,1476.33 1383.67,1476.33 v1(1400,1460) ; R28.1@1490,1192.76 1549.84,1192.76 R23.2@1550,1192.6
  Mid-Layer 1 w10: v1(1400,1460) 1520,1340 v1(1520,1192.76)
NetR33_2: R33.2 R35.2 U3.3 | length 124.2
  Top Layer w10: R33.2@1563.62,2400 1616.38,2400 R35.2@1620,2403.62 1623.58,2407.2 U3.3@1684.88,2407.2
NetR36_2: R36.2 U3.4 | length 94.6
  Top Layer w10: R36.2@1653.62,2300 1684.88,2331.26 U3.4@1684.88,2381.61
NetR38_1: R38.1 R40.2 U3.5 | length 157.7
  Top Layer w10: R40.2@1756.38,2240 1763.62,2247.24 R38.1@1763.62,2300 1795.12,2331.5 U3.5@1795.12,2381.61
NetR41_1: R41.1 U4.3 | length 399.8
  Top Layer w6: v1(2775,2065) 2785,2055 R41.1@2785,2043.62 ; R41.1@2782.5,2046.12 R41.1@2782.5,2051.12
  Top Layer w10: v1(2495,2145) 2495.1,2145.1 U4.3@2551.1,2145.1
  Mid-Layer 1 w6: v1(2495,2145) 2530,2110 2730,2110 v1(2775,2065)
NetR48_2: R48.2 U4.34 | length 72.2
  Top Layer w10: U4.34@2616.06,2200.22 R48.2@2616.06,2272.44
NetR49_2: R49.2 R53.2 U4.33 | length 201.7
  Top Layer w10: U4.33@2635.75,2200.22 2635.75,2246.9 2650,2261.15 2650,2303.62 R53.2@2680,2333.62 ; R53.2@2673.62,2340 R49.2@2673.62,2390
NetR54_2: R54.2 R55.2 U4.1 | length 153.5
  Top Layer w10: R55.2@2483.62,2310 R54.2@2483.62,2260 2551.1,2192.52 U4.1@2551.1,2184.47
NetR56_2: R56.2 R63.1 U7.1 | length 119.1
  Bottom Layer w10: R56.2@1392.82,1803.72 1424.91,1803.72 1440,1788.62 R63.1@1465,1788.62 ; 1465.85,1804.47 U7.1@1465.85,1845.09
NetR57_1: R57.1 R59.2 U5.5 | length 407.1
  Top Layer w10: U5.5@2043.12,1423.66 R57.1@2043.12,1535 2239.5,1535 2279.5,1495 2279.5,1453.76 R59.2@2280.6,1452.66
NetR62_1: R62.1 U7.7 | length 87.6
  Bottom Layer w10: U7.7@1680.42,1895.09 1751.3,1895.09 R62.1@1763.13,1883.26
NetR66_1: R66.1 U7.6 | length 88
  Bottom Layer w10: U7.6@1680.42,1945.09 1749.32,1945.09 R66.1@1762.82,1958.6
NetR71_1: R71.1 R80.2 T2.1 U12.7 | length 500.1
  Bottom Layer w10: U12.7@1679.79,2216.39 R80.2@1747.5,2216.39 ; R80.2@1772.5,2191.39 1772.5,2184.81 1815.92,2141.39 T2.1@2180.32,2141.39
NetR72_1: R72.1 R82.1 T2.3 U12.6 | length 500.7
  Bottom Layer w10: U12.6@1679.79,2266.39 R82.1@1747.5,2266.39 ; R82.1@1772.5,2291.39 1772.5,2299.05 1814.84,2341.39 T2.3@2180.32,2341.39
NetR73_1: R73.1 U9.7 | length 88.3
  Bottom Layer w10: U9.7@2250.1,1606.71 2319.32,1606.71 R73.1@2332.82,1593.2
NetR75_1: R75.1 U9.3 | length 81.2
  Bottom Layer w10: R75.1@1956.44,1661.71 1961.44,1656.71 U9.3@2035.54,1656.71
NetR76_1: R76.1 U9.2 | length 81.2
  Bottom Layer w10: R76.1@1956.44,1601.71 1961.44,1606.71 U9.2@2035.54,1606.71
NetR77_1: R77.1 U9.1 | length 85.3
  Bottom Layer w10: R77.1@1956.44,1541.71 1971.44,1556.71 U9.1@2035.54,1556.71
NetR78_1: R78.1 U9.6 | length 88.3
  Bottom Layer w10: U9.6@2250.1,1656.71 2319.32,1656.71 R78.1@2332.82,1670.21
NetR79_2: R79.2 U12.1 | length 87.4
  Bottom Layer w10: R79.2@1382.5,2155.02 1393.88,2166.39 U12.1@1465.22,2166.39
NetU4_19: U4.19 U4.20 U4.21 U4.22 U4.23 U4.24 | length 98.4
  Top Layer w10: U4.19@2680.67,1948.35 U4.20@2680.67,1968.04 U4.21@2680.67,1987.72 U4.22@2680.67,2007.41 U4.23@2680.67,2027.09 U4.24@2680.67,2046.78
PGOOD: D13.1 U2.6 | length 3222.9
  Top Layer w10: U2.6@1356.17,1456.65 1356.17,1438.83 v1(1375,1420)
  Mid-Layer 1 w10: v1(1375,1420) 1375,1470 1390,1485 1431.02,1485 1703.83,1212.19 2503.8,1212.19 2528.16,1236.56 2528.16,1537.89 2800,1809.73 2800,2537.09 2595,2742.09 v1(2595,2805)
  Bottom Layer w10: v1@2595.09,2798.76 D13.1@2595.09,2878.79
PHASE: D16.1 L2.1 R27.1 R31.2 U3.8 | length 3025.7
  Top Layer w10: v1(1512.2,2762.2) 1562.2,2762.2 1613.62,2710.77 R31.2@1613.62,2680 1670,2680 v1(1680,2670) ; v1(1760,2560) D16.1@1824.47,2560 1795.12,2530.65 U3.8@1795.12,2458.39 1977.28,2458.39 L2.1@1990,2471.1
  Top Layer w15: v1(1150,1175) 1188.62,1175 R27.1@1190,1176.38
  Mid-Layer 1 w10: v1(1150,1175) 1063.47,1175 870,1368.47 870,2495 900,2525 1275,2525 v1(1512.2,2762.2) ; v1(1680,2670) 1760,2590 v1(1760,2560)
PS_IMON: R11.2 R46.2 U4.2 | length 1748.3
  Top Layer w10: v1(1415,2000) 1756.36,2000 1926.97,2170.61 2265.66,2170.61 2283.67,2188.62 R46.2@2445,2188.62 2506.38,2188.62 2530.22,2164.78 U4.2@2551.1,2164.78
  Mid-Layer 1 w10: v1(995,1945) 1020,1970 1385,1970 v1(1415,2000)
  Bottom Layer w10: R11.2@991.5,1865 991.5,1941.5 v1(995,1945)
PWR_EN: D5.3 J8.1 R5.2 R15.2 | length 1820.5
  Top Layer w10: v1(844.05,1946.38) 856.08,1934.36 856.08,1529.52 955.29,1430.3 1029.7,1430.3 v1(1030,1430) R15.2@1066.38,1430
  Mid-Layer 1 w10: J8.1@770,2890 770,2888.45 844.23,2814.23 844.23,1946.56 v1(844.05,1946.38)
  Bottom Layer w10: R5.2@991.5,1530 1061.5,1460 D5.3@1070,1460 ; v1(1030,1430) 1040,1430 D5.3@1070,1460 ; D5.3@1082.76,1460 D5.3@1070,1460
PWR_FAULT: R1.2 R58.1 U4.30 | length 291.5
  Top Layer w10: U4.30@2681.02,2164.78 2740,2164.78 ; v1(2740,2185) 2740,2164.78 ; R58.1@2780,2168.5 2776.28,2164.78 2740,2164.78
  Bottom Layer w10: v1(2740,2185) 2740,2170 2830,2080 R1.2@2830,2051.5
RS485_DIR: D10.3 R6.2 U1.5 | length 1213.4
  Mid-Layer 1 w10: v1(1095,1900) 1135,1940 1395,1940 1460,2005 1525,2005 1690,1840 v1(1690,1695)
  Bottom Layer w6: D10.3@1082.76,1940 1082.76,1912.24 v1(1095,1900)
  Bottom Layer w7: v1(1690,1695) 1690,1680 1716.38,1653.62 U1.5@1716.38,1637.24
  Bottom Layer w10: R6.2@991.5,2150 991.5,2128.5 1082.76,2037.24 D10.3@1082.76,1940
RS485_RX: R2.2 U1.2 | length 1131.4
  Mid-Layer 1 w10: v1(995,2000) v1(1315,2000)
  Bottom Layer w6: v1@991.5,2003.5 v1(995,2000) ; R2.2@991.5,2050 R2.2@995,2046.5
  Bottom Layer w7: v1(1315,2000) 1306.83,1991.83 1306.83,1698.17 1422.87,1582.13 U1.2@1708.5,1582.13
  Bottom Layer w10: v1(995,2000) R2.2@995,2046.5
RS485_TX: D9.3 R8.2 U1.7 | length 1278.2
  Mid-Layer 1 w10: v1(1082.76,2135) 1600,2135 1765,1970 v1(1765,1675)
  Bottom Layer w7: U1.7@1747.87,1637.24 1747.87,1657.87 v1(1765,1675)
  Bottom Layer w10: R8.2@991.5,2250 1082.76,2158.74 v1(1082.76,2135) D9.3@1082.76,2100
VENCODER: C21.1 J6.4 J7.1 L5.1 Q5.1 Q5.2 Q5.3 R69.1 | length 1542.7
  Top Layer w10: Q5.1@2412.22,1355.06 Q5.3@2463.4,1355.06
  Top Layer w50: Q5.1@2419.5,1347.78 2419.86,1225 2420,1175 2470,1125 2725,1125 J7.1@3045,1445 3100,1445 3150,1495 3150,1611.69 J6.4@3359.37,1821.06
  Bottom Layer w50: J7.1@3045,1445 J7.1@3046.38,1443.62
  other v1: 2370,1290 2415,1290 2460,1290 2415,1320 2460,1320 2370,1325 2370,1360 2295,2235 2265,2260 2320,2260 2295,2290 2350,2290 2265,2320 2320,2320 2295,2350 2350,2350
VIN: C5.1 C6.1 C11.1 C12.1 C19.1 L6.2 R33.1 U2.2 U3.2 | length 628.2
  Top Layer w10: C6.1@1041.8,1495.43 C5.1@1121.8,1495.43 1142.08,1515.7 U2.2@1245.93,1515.7 ; C19.1@1110,2210 L6.2@1267.45,2210 ; R33.1@1516.38,2400 1516.38,2470.94 C11.1@1520,2474.56 C12.1@1600,2474.57 1615.43,2474.57 1657.2,2432.8 U3.2@1684.88,2432.8
VOUT: C25.2 R17.2 R41.2 R42.2 R53.1 R54.1 U4.29 | length 2483.9
  Top Layer w6: R42.2@2696.92,1845 2696.92,1890.55 2785,1978.63 R41.2@2785,1996.38
  Top Layer w10: v1(2395,2240) 2415,2260 R54.1@2436.38,2260 ; R53.1@2680,2281.38 2715,2246.38 v1(2715,2240) ; U4.29@2681.02,2145.1 2724.9,2145.1 v1(2740,2130) 2753.5,2130 C25.2@2778.5,2105 2820,2063.5 2820,2031.38 R41.2@2785,1996.38 ; R42.2@2710,1845 2710,1790 v1(2720,1790)
  Top Layer w50: R17.2@1520,1881.5 1701.5,1881.5 1946.36,2126.36 v1(2300,2126.36)
  Mid-Layer 1 w10: v1(2300,2126.36) 2636.36,1790 v1(2690,1790) v1(2720,1790) ; v1(2395,2240) v1@2710,2240 ; v1@2715,2235 2715,2155 v1(2740,2130)
  other v1: 2755,1825 2755,1860 2361.15,2117.02 2335.83,2139.29 2382.5,2143.56
VOUT_EFUSE: C22.1 D21.1 J15.2 Q5.5 Q5.6 Q5.7 Q5.8 Q5.9 R45.2 R60.2 U4.6 U4.7 U4.8 U4.9 U4.10 U4.11 U4.12 U4.13 | length 1635.9
  Top Layer w10: C22.1@2201.26,1850 2223.88,1850 2351.1,1722.78 ; Q5.9@2425.05,1452.66 R60.2@2330.6,1452.66 2330.6,1482.71 2351.1,1503.21 2351.1,1722.78 ; Q5.9@2484.2,1427.11 Q5.9@2450.6,1427.11 2450.6,1490.6 2493.5,1533.5 D21.1@2590.6,1533.5 ; U4.13@2550.75,1948.35 U4.12@2550.75,1968.04 ; U4.13@2551.1,1948.25 2551.1,1922.78 2351.1,1722.78 ; U4.12@2551.1,1967.93 U4.6@2551.1,2086.04 ; J15.2@2650,1662.5 2650,1592.9 D21.1@2590.6,1533.5 ; R45.2@2650.6,1352.66 2650.6,1473.5 D21.1@2590.6,1533.5
VPULL_UP: C31.2 R50.2 U1.10 | length 662
  Top Layer w10: v1(2170,1430) 2171,1431 v1@2171,1436 ; C31.2@2171,1475 v1@2171,1436 ; R50.2@2230.6,1452.66 2230.6,1494.4 2230,1495 v1@2171,1436
  Mid-Layer 1 w10: v1(1840,1625) 2035,1430 v1(2170,1430)
  Bottom Layer w7: U1.10@1771.5,1597.87 1795,1597.87 1822.13,1625 v1(1840,1625)
pads on no net: FID1.1 FID2.1 FID3.1 H1.1 H2.1 H3.1 H7.0 J6.9 J6.11 J6.14 J6.16 J6.17 Logo1.0 T2.2 T2.5 U4.25

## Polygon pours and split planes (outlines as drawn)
GND on Top Layer "Top Layer-No Net 9" (solid, pour order 197): 450,3100 500,3150 2950,3150 2995,3105 2995,1100 2994.96,1100 2944.96,1050 500,1050 450,1100 450,3100
3.3V on Top Layer "Top Layer-No Net 9" (solid, pour order 104): 1766.05,1135.1 1835.1,1135.1 1837.75,1137.75 1840,1140 1840,1217.63 1828.36,1217.63 1772.38,1161.65
VOUT on Top Layer "Top Layer-No Net 9" (solid, pour order 105): 1522.09,1856.65 1505.2,1856.65 1495.14,1866.71 1491.98,1869.87 1491.98,1888.66 1491.98,1894.48 1491.98,1899.61 1498.83,1906.46 1503.96,1906.46 1522.5,1906.46 1522.5,1877.35 1525.33,1874.52
NetD18_2 on Top Layer "Top Layer-No Net 9" (solid, pour order 193): 1130,2700 1130,2589.83 1130.65,2589.18 1163.79,2556.04 1163.79,2535.89 1163.79,2506.17 1199.31,2470.65 1205.12,2464.84 1290.17,2464.84 1310,2484.67 1310,2700 1290,2720 1150,2720
3.3V on Top Layer "Top Layer-No Net 9" (solid, pour order 190): 2120,1555 2205,1555 2215,1565 2215,1580 2170,1625 2100,1695 2075,1695 1940,1695 1895,1740 1855,1780 1810,1780 1800,1770 1800,1740 1860,1680 1860,1665 1860,1600 1835,1575 1835,1460 1810,1435 1810,1310 1830,1310 1915,1395 1915,1400 1915,1550 1930,1565 2110,1565
3.3V on Top Layer "Top Layer-No Net 9" (solid, pour order 116): 1015,1305 990,1330 990,1375 1020,1405 1065,1405 1075,1405 1085,1395 1085,1355 1085,1345 1045,1305
VENCODER on Top Layer "Top Layer-No Net 9" (solid, pour order 174): 2355,1370 2355,1275 2365,1265 2395,1265 2460,1265 2480,1285 2480,1330 2475,1335 2475,1370 2470,1375 2360,1375
GND on Top Layer "Top Layer-No Net 9" (solid, pour order 165): 2520,1221.84 2608.16,1221.84 2610,1220 2615,1215 2625,1215 2630,1220 2630,1255 2625,1260 2520,1260
NetD15_3 on Top Layer "Top Layer-No Net 9" (solid, pour order 156): 1055,1235 1055,1205 1060,1200 1085,1200 1090,1205 1205,1205 1230,1230 1290,1230 1295,1235 1295,1310 1290,1315 1260,1315 1190,1245 1125,1245 1060,1245 1055,1240
GND on Top Layer "Top Layer-No Net 9" (solid, pour order 154): 1090,1330 1100,1340 1125,1340 1165,1380 1165,1395 1170,1400 1195,1400 1200,1395 1200,1340 1185,1325 1145,1325 1115,1295 1095,1295 1090,1300
NetC1_1 on Top Layer "Top Layer-No Net 9" (solid, pour order 121): 1040,1630 1035,1635 1035,1720 1040,1725 1080,1725 1085,1720 1085,1640 1085,1635 1080,1630
GND on Top Layer "Top Layer-No Net 9" (solid, pour order 152): 2820,2085 2865,2085 2895,2115 2895,2135 2865,2165 2860,2165 2840,2165 2820,2145 2820,2085
VOUT on Top Layer "Top Layer-No Net 9" (solid, pour order 151): 2680,1870 2680,1880 2690,1880 2695,1880 2760,1880 2780,1860 2780,1825 2720,1765 2685,1765 2680,1770
VPULL_UP on Top Layer "Top Layer-No Net 8" (solid, pour order 142): 2150,1490 2150,1420 2165,1405 2175,1405 2180,1405 2205,1430 2210,1435 2245,1435 2250,1440 2250,1485 2225,1510 2165,1510 2150,1495
NetC24_1 on Top Layer "Top Layer-No Net 7" (solid, pour order 139): 2265,1415 2265,1315 2270,1310 2340,1310 2345,1315 2345,1420 2340,1425 2270,1425 2265,1420
PHASE on Top Layer "Top Layer -PHASE" (solid, pour order 132): 1790,2450 1830,2450 1845,2450 1875,2420 1895,2420 2095,2420 2105,2430 2105,2505 2105,2510 2095,2520 1885,2520 1850,2555 1850,2585 1840,2595 1770,2595 1740,2565 1740,2555 1780,2515 1785,2510 1785,2455 1790,2450
VOUT_EFUSE on Top Layer "Top Layer -VOUT_EFUSE" (solid, pour order 129): 2560,2090 2315,2090 2115,1890 2115,1750 2115,1700 2315,1500 2315,1440 2320,1435 2360,1435 2395,1400 2395,1390 2400,1385 2505,1385 2510,1390 2510,1405 2570,1465 2660,1465 2685,1490 2685,1590 2685,1725 2675,1735 2625,1735 2620,1730 2620,1710 2600,1690 2525,1690 2505,1710 2505,1850 2560,1905 2560,2085 2560,2090
NetJ15_1 on Top Layer "Top Layer-No Net 1" (solid, pour order 134): 2530,1705 2595,1705 2605,1715 2605,1740 2615,1750 2645.76,1750 2655,1759.24 2655,1895 2660,1900 2660,1970 2575,1970 2575,1905 2575,1900 2520,1845 2520,1715
NetC2_1 on Top Layer "Top Layer-No Net 2" (solid, pour order 137): 1320,1975 1320,1725 1410,1725 1410,1665 1630,1665 1630,1755 1545,1840 1500,1840 1390,1950 1390,1960 1375,1975 1320,1975
NetD14_1 on Top Layer "Top Layer-No Net 3" (solid, pour order 135): 1350,1530 1630,1530 1630,1615 1625,1620 1400,1620 1385,1635 1385,1690 1370,1705 1340,1705 1325,1690 1325,1615 1345,1595 1345,1530
NetC16_1 on Top Layer "Top Layer-No Net 4" (solid, pour order 140): 1080,2260 1130,2260 1145,2275 1185,2275 1335,2275 1340,2280 1340,2410 1300,2450 1200,2450 1150,2500 1150,2550 1130,2570 1085,2570 1080,2565 1075,2560 1075,2266.5
VIN on Top Layer "Top Layer -VIN" (solid, pour order 141): 1085,2245 1080,2245 1075,2240 1075,2175 1080,2170 1105,2145 1200,2145 1310,2145 1335,2170 1350,2185 1425,2260 1425,2295 1425,2325 1480,2380 1530,2380 1535,2385 1535,2425 1545,2435 1645,2435 1655,2425 1690,2425 1695,2430 1695,2435 1690,2440 1665,2440 1635,2470 1635,2495 1625,2505 1470,2505 1355,2390 1355,2335 1355,2270 1345,2260 1340,2260 1155,2260 1140,2245 1080,2245
NetC13_1 on Top Layer "Top Layer-No Net 6" (solid, pour order 143): 1790,2640 1800,2630 1865,2630 1875,2620 1875,2615 1875,2575 1875,2570 1885,2560 2090,2560 2095,2560 2100,2565 2100,2575 2100,2720 2090,2730 2055,2730 1950,2730 1880,2800 1830,2800 1795,2800 1790,2795
VENCODER on Top Layer "Top Layer -VENCODER" (solid, pour order 144): 2400,1370 2395,1365 2395,1260 2400,1255 2440,1255 2445,1260 2445,1305 2445,1310 2475,1340 2475,1370 2400,1370
GND on Top Layer "Top Layer -GND" (solid, pour order 145): 1705,2335 1775,2335 1770,2335 1770,2500 1720,2550 1720,2570 1775,2625 1775,2650 1775,2800 1765,2810 1715,2810 1705,2800 1705,2630 1655,2580 1490,2580 1480,2570 1480,2525 1490,2515 1635,2515 1650,2530 1680,2530 1695,2515 1710,2500 1710,2485 1710,2335
GND on Top Layer "Top Layer-No Net 9" (solid, pour order 107): 2830,2695 2840,2705 2885,2705 2910,2680 2910,2655 2890,2635 2875,2635 2855,2635 2830,2660
GND on Top Layer "Top Layer-No Net 9" (solid, pour order 115): 1010,1585 1020,1595 1165,1595 1185,1615 1200,1630 1200,1800 1200,1930 1250,1980 1290,1980 1300,1970 1300,1675 1300,1670 1310,1660 1310,1605 1330,1585 1330,1525 1330,1435 1330,1430 1360,1400 1390,1400 1415,1425 1415,1435 1425,1445 1450,1445 1455,1440 1455,1315 1455,1320 1400,1265 1400,1240 1340,1180 1270,1180 1260,1190 1260,1215 1265,1220 1340,1220 1375,1255 1375,1320 1375,1325 1355,1345 1305,1345 1300,1345 1295,1350 1295,1410 1270,1435 1270,1440 1270,1545 1250,1565 1200,1565 1180,1565 1165,1550 1155,1540 1125,1540 1015,1540 1010,1545 1010,1585
VIN on Top Layer "Top Layer-No Net 9" (solid, pour order 117): 1255,1510 1195,1510 1150,1465 1145,1465 1150,1465 1145,1460 1130,1460 1005,1460 990,1475 990,1515 990,1518.5 996.5,1525 1175,1525 1180,1520 1255,1520
VIN on Top Layer "Top Layer-No Net 9" (solid, pour order 118): 1080,2190 1070,2180 1070,2171.5 1058.5,2160 1045,2160 980,2160 880,2060 880,1720 880,1585 1005,1460 1015,1460 1015,1515 995,1535 995,1540 995,1590 1000,1595 1025,1620 1025,1735 1025,2025 1100,2100 1250,2100 1265,2100 1316.58,2151.58
VIN on Top Layer "Top Layer-No Net 9" (solid, pour order 119): 1276.55,2111.55 1180,2015 1180,1850 1125,1795 1040,1795 1075,1795 1005,1725 935,1795 935,1940 935,2035 1010,2110 1045,2145 1220,2145
VIN on Top Layer "Top Layer-No Net 9" (solid, pour order 124): 880,1595 880,1530 950,1460 975,1460 1030,1460 990,1500 990,1515
GND on Top Layer "Top Layer-No Net 9" (solid, pour order 123): 2630,2315 2645,2330 2645,2375 2645,2405 2635,2415 2545,2415 2550,2415 2540,2425 2540,2445 2520,2465 2520,2475 2505,2490 2485,2470 2505,2490 2496.52,2490 2495,2488.48 2495,2460 2520,2435 2520,2405 2520,2340 2535,2325 2580,2325 2585,2325 2595,2315 2605,2315
GND on Top Layer "Top Layer-No Net 9" (solid, pour order 126): 2520,2385 2500,2365 2500,2345 2510,2335 2525,2335 2528.43,2331.57 2565,2365
NetC13_1 on Top Layer "Top Layer-No Net 9" (solid, pour order 166): 1870,2800 1910,2800 1990,2720 1990,2705 1880,2705
GND on Top Layer "Top Layer-No Net 9" (solid, pour order 168): 1865,1225 1865,1285 1890,1310 2130,1310 2140,1300 2340,1300 2345,1295 2345,1275 2370,1250 2380,1240 2380,1180 2330,1130 1890,1130 1865,1155 1865,1225
VENCODER on Top Layer "Top Layer-No Net 9" (solid, pour order 170): 2380,1265 2395,1250 2414.77,1250 2435,1250 2450,1265 2450,1270 2445,1270 2414.71,1270 2380,1270
GND on Top Layer "Top Layer-No Net 9" (solid, pour order 171): 2880,2100 2975,2195 2975,2265 3010,2300 3075,2300 3095,2320 3095,2375 3080,2390 3010,2390 2975,2425 2975,2480 2975,2615 2895,2695 2880,2680 2830,2680 2830,2190 2820,2180 2820,2135 2825,2130
NetC4_1 on Top Layer "Top Layer-No Net 9" (solid, pour order 178): 2170,1310 2240,1310 2250,1320 2250,1415 2240,1425 2214.42,1425 2187.21,1397.79 2164.42,1375 2015,1375 2005,1385 2005,1420 1985,1420 1985,1360 2020,1325 2155,1325
NetD21_2 on Top Layer "Top Layer-No Net 9" (solid, pour order 177): 2640.3,1320.63 2620.34,1340.59 2620.34,1420.74 2612.01,1429.07 2609.92,1429.07 2569.2,1429.07 2562,1421.88 2562,1414.87 2516.92,1369.79 2490.6,1369.79 2487,1366.19 2487,1342.7 2489.84,1339.86 2535.3,1339.86 2559.16,1316 2559.73,1315.43 2587.19,1315.43 2613.71,1288.91 2639.85,1288.91 2641.93,1291 2641.93,1293.84
VENCODER on Top Layer "Top Layer-No Net 9" (solid, pour order 183): 2385.45,2369.94 2276.48,2369.94 2241.09,2334.54 2241.09,2209.54 2246.09,2204.54 2321.09,2204.54 2391.09,2274.54 2391.38,2363.98
VOUT on Top Layer "Top Layer-No Net 9" (solid, pour order 188): 2275,2115 2275,2140 2295,2160 2340,2160 2350,2170 2380,2170 2410,2140 2410,2106.36 2403.64,2100 2290,2100
VIN on Top Layer "Top Layer-No Net 9" (solid, pour order 187): 1635,2495 1656.12,2473.88 1656.12,2452.73 1671.04,2437.81 1671.04,2432.8 1654.47,2432.8 1624.38,2462.88 1615.58,2495
VOUT on Top Layer "Top Layer-No Net 9" (solid, pour order 114): 2685,1765 2670,1780 2670,1790 2670,1865.46 2684.54,1880 2705,1880 2705,1765
3.3V on Bottom Layer "Top Layer-No Net 9" (solid, pour order 191): 1115.19,2376.01 1115.19,2442.78 1114.44,2443.52 1118.9,2439.06 1127.93,2439.06 1155.44,2411.55 1155.44,2406.66
3.3V on Bottom Layer "Top Layer-No Net 9" (solid, pour order 113): 1015,1305 990,1330 990,1375 1020,1405 1065,1405 1075,1405 1085,1395 1085,1355 1085,1345 1045,1305
VOUT on Bottom Layer "Top Layer-No Net 9" (solid, pour order 150): 2680,1870 2680,1880 2690,1880 2695,1880 2760,1880 2780,1860 2780,1825 2720,1765 2685,1765 2680,1770
VENCODER on Bottom Layer "Top Layer-No Net 9" (solid, pour order 173): 2355,1370 2355,1275 2365,1265 2395,1265 2460,1265 2480,1285 2480,1330 2475,1335 2475,1370 2470,1375 2360,1375
3.3V on Bottom Layer "Top Layer-No Net 9" (solid, pour order 176): 1850,1600 1890,1640 1900,1630 1900,1585
3.3V on Bottom Layer "Top Layer-No Net 9" (solid, pour order 175): 1805,1755 1865,1695 1865,1600 1907.49,1600 1909.2,1601.71 1885,1625.91 1885,1760
VENCODER on Bottom Layer "Top Layer-No Net 9" (solid, pour order 167): 2205,2645 2190,2630 2190,2435 2190,2425 2205,2410 2220,2410 2245,2385 2245,2330 2245,2190 2255,2180 2360,2180 2370,2190 2370,2360 2290,2440 2290,2445 2290,2630 2275,2645
GND on Bottom Layer "Top Layer-No Net 9" (solid, pour order 162): 2380,1685 2390,1695 2460,1695 2530,1625 2600,1625 2985,1625 2990,1625 2995,1620 2995,1555 2990,1550 2970,1550 2445,1550 2425,1570 2420,1570 2390,1570 2380,1580
DSL2- on Bottom Layer "Top Layer-No Net 9" (solid, pour order 160): 2405,1845 2520,1845 2565,1890 2590,1915 2515,1940 2490,1940 2425,1940 2410,1925
GND on Bottom Layer "Top Layer-No Net 9" (solid, pour order 158): 2280,1840 2285,1845 2285,2055 2275,2065 2140,2065 2100,2025 2100,2000 2100,1890 2150,1840
3.3V on Bottom Layer "Top Layer-No Net 9" (solid, pour order 146): 1650,2180 1705,2180 1710,2175 1710,2155 1680,2125 1680,2105 1680,2035 1670,2025 1640,2025 1630,2035 1630,2075 1630,2160 1650,2180
DSL2+ on Bottom Layer "Bottom Layer-No Net 3" (solid, pour order 130): 2395,2620 2409.33,2634.33 2418.27,2634.33 2420.67,2634.33 2425,2630 2430,2625 2430,2610 2430,2595 2465,2560 2530,2560 2535,2555 2535,2545 2535,2505 2530,2500 2465,2500 2425,2460 2425,2440 2425,2432.4 2418.27,2425.67 2417.6,2425 2410,2425 2410,2605 2395,2620
DSL2- on Bottom Layer "Bottom Layer-No Net 2" (solid, pour order 127): 2418.27,2054.33 2425,2047.6 2425,1990 2425,2005 2450,1980 2460,1980 2520,1980 2525,1975 2525,1965 2525,1925 2520,1920 2450,1920 2425,1895 2425,1885 2425,1852.4 2418.27,1845.67 2395,1868.94 2395,1895 2395,2031.06 2418.27,2054.33
3.3V on Bottom Layer "Bottom Layer-No Net" (solid, pour order 125): 1660,1860 1640,1840 1640,1785 1635,1780 1635,1740 1640,1735 1675,1735 1680,1735 1695,1750 1850,1750 1885,1715 1885,1695 1885,1610 1880,1605 1825,1605 1805,1585 1796.94,1583.06 1805,1575 1820,1560 1835,1560 1870,1560 1885,1545 1885,1530 1895,1520 1925,1520 1930,1525 1930,1565 1930,1740 1895,1775 1855,1775 1685,1775 1735,1775 1691.21,1790 1735,1775 1720,1790 1735,1775 1725,1785 1725,1850 1715,1860
GND on Bottom Layer "Bottom Layer -GND" (solid, pour order 131): 1760,1570 1760,1525 1790,1495 1865,1495 1870,1500 1870,1540 1865,1545 1820,1545 1815,1545 1790,1570 1760,1570
3.3V on Bottom Layer "Top Layer-No Net 9" (solid, pour order 120): 1135,2400 1115,2380 1115,2355 1115,1445 1075,1405 1035,1405 1020,1405 1015,1400 1005,1390 1005,1305 1015,1295 1050,1295 1160,1405 1185,1405 1195,1405 1205,1415 1205,1430 1190,1445 1155,1445 1145,1455 1145,1535 1145,1550 1160,1565 1180,1565 1195,1565 1205,1575 1205,1580 1205,1590 1195,1600 1150,1600 1140,1610 1140,1705 1160,1725 1190,1725 1195,1725 1205,1735 1205,1755 1195,1765 1145,1765 1150,1765 1145,1770 1145,1865 1165,1885 1180,1885 1200,1885 1205,1890 1205,1910 1195,1920 1155,1920 1145,1930 1145,2010 1145,2030 1155,2040 1160,2045 1195,2045 1205,2055 1205,2070 1195,2080 1160,2080 1145,2095 1145,2110 1145,2185 1165,2205 1185,2205 1195,2205 1205,2215 1205,2230 1195,2240 1165,2240 1145,2260 1145,2275 1145,2345 1165,2365 1195,2365 1205,2375 1205,2395 1195,2405 1140,2405
3.3V on Bottom Layer "Top Layer-No Net 9" (solid, pour order 122): 1020,1390 1005,1390 990,1375 990,1320 1015,1295 1055,1335 1055,1350
3.3V on Bottom Layer "Top Layer-No Net 9" (solid, pour order 128): 1130,2395 1150,2415 1180,2415 1215,2415 1245,2445 1730,2930 1730,2970 1745,2985 2255,2985 2265,2975 2265,2910 2250,2895 1825,2895 1300,2370 1275,2345 1155,2345 1140,2330 1140,2325 1130,2335 1130,2390
GND on Bottom Layer "Top Layer-No Net 9" (solid, pour order 133): 1985,2320 1990,2325 2035,2325 2060,2300 2060,2260 2060,2180 2040,2160 1985,2160 1975,2170 1975,2310
GND on Bottom Layer "Top Layer-No Net 9" (solid, pour order 138): 1385,2075 1345,2075 1320,2050 1320,2030 1335,2015 1335,1990 1335,1920 1360,1895 1405,1895 1410,1900 1410,1995 1410,2005 1390,2025 1390,2070
3.3V on Bottom Layer "Top Layer-No Net 9" (solid, pour order 153): 2205,1450 2200,1455 2200,1525 2175,1550 2175,1600 2185,1610 2200,1610 2210,1600 2210,1580 2215,1575 2265,1575 2270,1575 2285,1560 2285,1485 2250,1450
3.3V on Bottom Layer "Top Layer-No Net 9" (solid, pour order 155): 2190,1610 2160,1610 2150,1600 2150,1575 2210,1515
3.3V on Bottom Layer "Top Layer-No Net 9" (solid, pour order 157): 1637.5,2062.5 1580,2005 1580,1840 1580,1820 1620,1780 1620,1735 1620,1730 1625,1730 1675,1730 1683.61,1730 1715,1761.39 1715,1805 1630,1890 1630,2000 1665,2035
3.3V on Bottom Layer "Top Layer-No Net 9" (solid, pour order 159): 1720,1795 1745,1770 1723.61,1770 1715,1761.39
GND on Bottom Layer "Top Layer-No Net 9" (solid, pour order 164): 1675,2005 1700,2030 1700,2070 1700,2115 1725,2140 1790,2140 1815,2115 1840,2090 1840,2070 1830,2060 1820,2060 1745,2060 1715,2030 1715,1995 1705,1985 1675,1985 1675,1990 1670,1995
GND on Bottom Layer "Top Layer-No Net 9" (solid, pour order 136): 1655,2330 1665,2340 1665,2360 1650,2375 1620,2375 1580,2375 1560,2355 1560,2270 1575,2255 1615,2255 1625,2265 1625,2310 1625,2315 1640,2330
